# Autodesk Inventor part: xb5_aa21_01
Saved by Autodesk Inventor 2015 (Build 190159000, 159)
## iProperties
Created: 2018-05
Part Number: xb5_aa21_01
Checked By: TraceParts S.A.
Material: Generic
Catalog Web Link: www.traceparts.com
Document SubType Name: Modeling
Designer: TraceParts
Density: 1 g/cm^3
Appearance: Default
Company: TraceParts S.A.
Author: TraceParts
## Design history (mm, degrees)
feature "xb5_aa21_01.ipt"
body "Solid1"
